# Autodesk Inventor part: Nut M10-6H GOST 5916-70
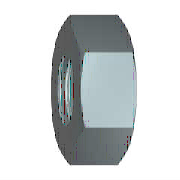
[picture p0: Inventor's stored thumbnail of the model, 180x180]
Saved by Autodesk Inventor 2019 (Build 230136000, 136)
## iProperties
Created: 2018-01
Part Number: Nut M10-6H GOST 5916-70
Material: Steel, Mild
Description: Hexagon lock-nuts,product grade В
Document SubType Name: Modeling
Standard: GOST 5916
Designer: m.vorobev
Standards Organization: GOST
Language: en-US
Size Designation: M10
Categories: <MemberInstance><Categories><Category DisplayName="Fasteners" InternalName="e4da775c-781d-43d5-af7c-5136215cf5a6" Mnemonic="FSTN"><Category DisplayName="Nuts" I
Density: 7.85 g/cm^3
Appearance: Semi-Polished
IsCustomPart: 0
Author: m.vorobev
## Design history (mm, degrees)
sketch "Sketch1"
  geometry: L1 (-9.815, 0)-(-4.907, 8.5); L2 (-4.907, 8.5)-(4.907, 8.5); L3 (4.907, 8.5)-(9.815, 0); L4 (9.815, 0)-(4.907, -8.5); L5 (4.907, -8.5)-(-4.907, -8.5); L6 (-4.907, -8.5)-(-9.815, 0); 2 further points
  constraints: 12 end point, 1 coincident, 1 horizontal, 11 other
  dimensions: "d0" = 19.62991 distance of L3.end L1.start (= 1.1547 x SW)
extrude "Body" new body sketch "Sketch1" distance "d1" = 6 (= KOH); taper "d2" = 0 deg
sketch "Sketch2"
  geometry: L1 (0, 4.907)-(0, 9.815) reference; L2 (0, 9.815)-(6, 9.815) reference; L3 (6, 4.907)-(6, 9.815) reference; L4 (-1.2, 0)-(7.2, 0) reference; L5 (1.25, 9.815)-(0, 7.65); L6 (4.75, 9.815)-(6, 7.65)
  constraints: 4 end point, 4 point on line
  dimensions: "d3" = 30 deg angle of L1 L5 (= ANG1); "d4" = 30 deg angle of L3 L6 (= ANG2); "d5" = 15.3 diameter of L5.end L4 (= SW0); "d6" = 15.3 diameter of L6.end L4 (= SW01)
revolve "Chamfer1" sketch "Sketch2" stored, may be unused: angle "d7" = 90 deg
sketch "Sketch3"
  geometry: 4 further points
  constraints: 1 coincident, 1 other
hole "Thread" sketch "Sketch3" at (0, 0) diameter "d25" = 8.376; stored, may be unused: countersink angle "d29" = 82 deg, drill point angle "d31" = 118 deg; dims "d26" = 6, "d27" = 4, "d28" = 2, "d30" = 8
workaxis "Work Axis1"
workplane "Work Plane1"
body "Solid1"
chamfer "Chamfer2" distance "d8" = 0.8119 (= -0.5 x GD1 + 0.5 x NND); stored, may be unused: angle "d9" = 30 deg, second distance "d40" = 0.8119 (= -0.5 x GD1 + 0.5 x NND)
chamfer "Chamfer3" distance "d10" = 0.8119 (= -0.5 x GD1 + 0.5 x NND); stored, may be unused: angle "d11" = 30 deg, second distance "d41" = 0.8119 (= -0.5 x GD1 + 0.5 x NND)
other parameters: "ANG1" = 30 deg [user parameter; used in 1 equation term], "ANG2" = 30 deg [user parameter; used in 1 equation term], "KOH" = 6 [user parameter; used in 1 equation term], "SW" = 17 [user parameter; used in 2 equation terms], "SW0" = 15.3 [user parameter; used in 1 equation term], "SW01" = 15.3 [user parameter; used in 1 equation term], "GD1" = 8.3762 (computed from THREADDIA, PTC, TOA) [user parameter; used in 4 equation terms], "d13" = 0, "d14" = 0, "d39" = 0, "d42" = 0, "GUL" = 0.8119 (= 0.541266 x PTC) [user parameter], "TPU" = 6.66667 (computed from PTC) [user parameter], "LADI" = 16.15 [user parameter], "TOA" = 30 deg [user parameter; used in 1 equation term], "FAWI" = 30 deg [user parameter], "PTC" = 1.5 [user parameter; used in 4 equation terms], "E0" = 19.635 (= 1.155 x SW) [user parameter], "GAL" = 0.8119 (= 0.541266 x PTC) [user parameter]
